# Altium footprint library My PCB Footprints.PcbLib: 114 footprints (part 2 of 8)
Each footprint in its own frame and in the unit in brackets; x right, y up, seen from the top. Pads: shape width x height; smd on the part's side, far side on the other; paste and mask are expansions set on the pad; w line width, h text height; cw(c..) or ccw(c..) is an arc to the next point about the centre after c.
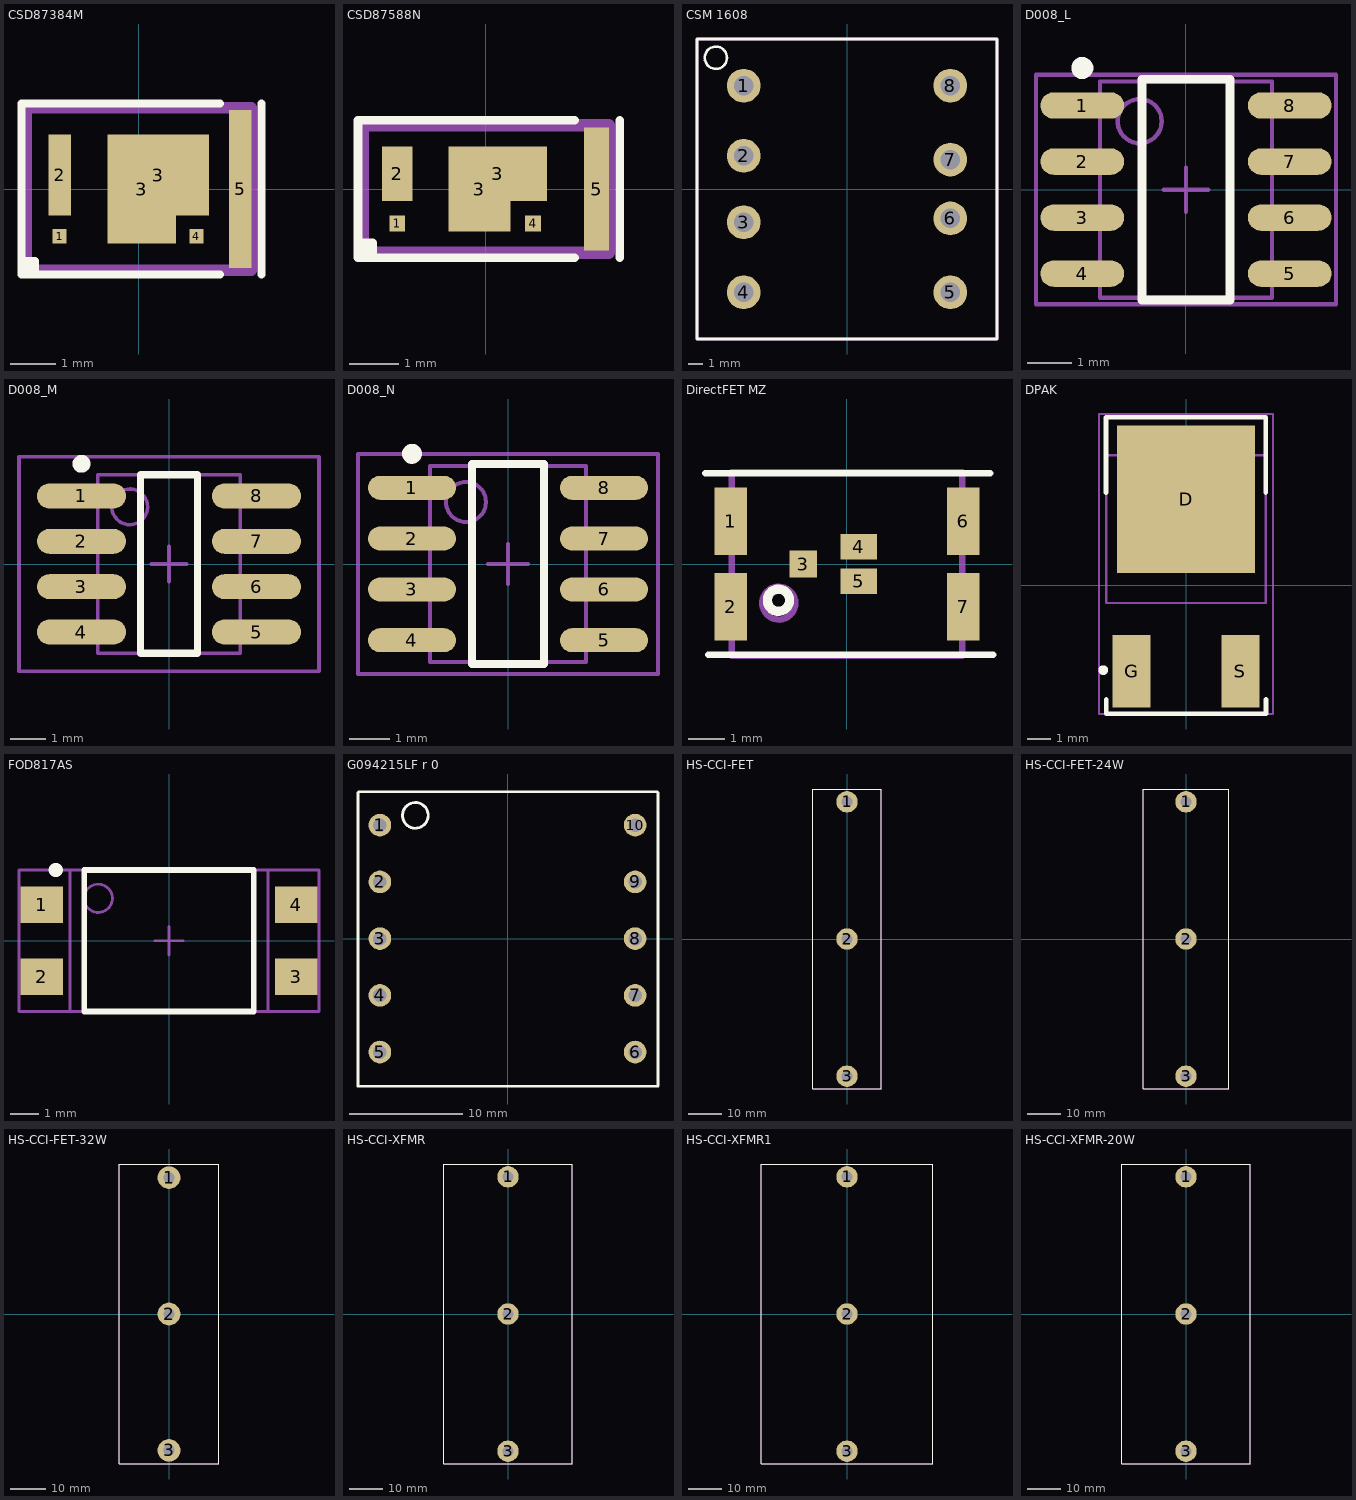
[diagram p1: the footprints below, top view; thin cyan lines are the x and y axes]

## CSD87384M [mm] "TI recommended land pattern SLPS-JUNE 2012"
height 0.45
pads (6):
  rect 0.32x0.32 smd paste+0 mask+0.051: 1(-1.76,-1.05) 4(1.28,-1.05)
  rect 0.5x1.8 smd paste-0.1 mask+0.051: 2(-1.76,0.31)
  rect 1.52x2.42 smd paste-1.5 mask+0.051: 3(0.06,0)
  rect 2.26x1.8 smd paste-2.2 mask+0.051: 3(0.43,0.31)
  rect 0.5x3.5 smd paste-0.5 mask+0.051: 5(2.25,0)
Top Overlay:
  lines w0.178: -2.6,-1.75 -2.3,-1.75 ; -2.6,-1.6 -2.3,-1.6 -2.3,-1.9 ; 1.8,-1.9 0,-1.9 -2.6,-1.9 -2.6,0 -2.6,1.9 0,1.9 1.8,1.9 ; 2.72,-1.9 2.72,0 2.72,1.9
Top Paste:
  region: -0.6,-0.39 -0.6,1.11 0.33,1.11 0.33,-0.39
  region: 1.46,-0.39 0.53,-0.39 0.53,1.11 1.46,1.11
  region: 2.08,-1.67 2.08,-0.1 2.42,-0.1 2.42,-1.67
  region: 2.08,0.1 2.08,1.67 2.42,1.67 2.42,0.1
  region: 0.72,-1.11 -0.6,-1.11 -0.6,-0.59 0.72,-0.59
Mechanical 5:
  text ".Designator" at -1.529,-0.508 h1.02
Mechanical 13:
  lines w0.254: -2.5,-1.8 2.5,-1.8 2.5,1.8 -2.5,1.8 -2.5,-1.8
3D body: height 1.5, standoff 0, extent -2.5,-1.8 2.5,1.8
3D body: height 1.5, standoff 1.5, extent -2.5,-1.8 0,0

## CSD87588N [mm] "TI recommended land pattern SLPS-JUNE 2012"
height 0.45
pads (6):
  rect 0.32x0.32 smd paste+0 mask+0.051: 1(-1.8,-0.7) 4(0.96,-0.7)
  rect 0.62x1.1 smd paste-0.1 mask+0.051: 2(-1.8,0.31)
  rect 1.26x1.72 smd paste-1.5 mask+0.051: 3(-0.13,0)
  rect 2x1.1 smd paste-2.2 mask+0.051: 3(0.24,0.31)
  rect 0.5x2.5 smd paste-0.08 mask+0.051: 5(2.25,0)
Top Overlay:
  lines w0.178: -2.6,-1.25 -2.3,-1.25 ; -2.6,-1.1 -2.3,-1.1 -2.3,-1.4 ; 1.8,-1.4 0,-1.4 -2.6,-1.4 -2.6,0 -2.6,1.4 0,1.4 1.8,1.4 ; 2.72,-1.4 2.72,0 2.72,1.4
Top Paste:
  region: 0.4,-0.76 -0.66,-0.76 -0.66,-0.34 0.4,-0.34
  region: 1.14,-0.14 0.34,-0.14 0.34,0.76 1.14,0.76
  region: -0.66,-0.14 -0.66,0.76 0.14,0.76 0.14,-0.14
Mechanical 5:
  text ".Designator" at -1.529,-0.508 h1.02
Mechanical 13:
  lines w0.254: -2.5,-1.3 -2.5,1.3 2.5,1.3 2.5,-1.3 -2.5,-1.3
3D body: height 1.5, standoff 1.5, extent -2.5,-1.3 0,0
3D body: height 1.5, standoff 0, extent -2.5,-1.3 2.5,1.3

## CSM 1608 [mil] "Cramer Coil Offline Flyback Transformer"
height 650
pads (8):
  round 90 hole 52: 1(-275.5,275.5) 2(-275.5,88.5) 3(-275.5,-88.5) 4(-275.5,-275.5) 5(275.5,-275.5) 6(275.5,-78.5) 7(275.5,78.5) 8(275.5,275.5)
Top Overlay:
  circle w7: c-349.73,350 r29.73
  lines w7: -400,-400 400,-400 400,400 -400,400 -400,-400
Mechanical 5:
  text ".designator" at -48,-25 h60
Mechanical 13:
  lines w7: -400,-400 400,-400 400,400 -400,400 -400,-400
3D body: height 600, standoff 50, extent -400,-400 400,400
3D body: height 650, standoff 649, extent -378.06,321.46 -318.12,381.4

## D008_L [mm] "8-Pin Small Outline Integrated Circuit 1.27 mm Pitch, IPC High Density"
height 1.75
pads (8):
  oval 1.9x0.6 smd: 1(-2.35,1.905) 2(-2.35,0.635) 3(-2.35,-0.635) 4(-2.35,-1.905) 5(2.35,-1.905) 6(2.35,-0.635) 7(2.35,0.635) 8(2.35,1.905)
Top Overlay:
  circle w0.25: c-2.35,2.755 r0.125
  lines w0.2: -1,-2.5 -1,2.5 1,2.5 1,-2.5 -1,-2.5
Mechanical 5:
  text ".Designator" at -0.254,1.524 h1.02
Mechanical 13:
  circle w0.1: c-1.05,1.55 r0.5
  lines w0.1: -1.95,-2.45 -1.95,2.45 1.95,2.45 1.95,-2.45 -1.95,-2.45
Mechanical 15:
  lines w0.1: -0.5,0 0.5,0 ; 0,-0.5 0,0.5 ; -3.4,-2.6 -3.4,2.6 3.4,2.6 3.4,-2.6 -3.4,-2.6
3D body: height 1.75, standoff 0, extent -1.95,-2.45 1.95,2.45

## D008_M [mm] "8-Pin Small Outline Integrated Circuit 1.27 mm Pitch, IPC Low Density"
height 1.75
pads (8):
  oval 2.5x0.7 smd: 1(-2.45,1.905) 2(-2.45,0.635) 3(-2.45,-0.635) 4(-2.45,-1.905) 5(2.45,-1.905) 6(2.45,-0.635) 7(2.45,0.635) 8(2.45,1.905)
Top Overlay:
  circle w0.25: c-2.45,2.805 r0.125
  lines w0.2: -0.8,-2.5 0.8,-2.5 0.8,2.5 -0.8,2.5 -0.8,-2.5
Mechanical 5:
  text ".Designator" at -0.254,1.524 h1.02
Mechanical 13:
  circle w0.1: c-1.1,1.6 r0.5
  lines w0.1: -2,-2.5 2,-2.5 2,2.5 -2,2.5 -2,-2.5
Mechanical 15:
  lines w0.1: -0.5,0 0.5,0 ; 0,-0.5 0,0.5 ; -4.2,-3 4.2,-3 4.2,3 -4.2,3 -4.2,-3
3D body: height 1.75, standoff 0, extent -2,-2.5 2,2.5

## D008_N [mm] "8-Pin Small Outline Integrated Circuit 1.27 mm Pitch, IPC Medium Density"
height 1.75
pads (8):
  oval 2.2x0.6 smd: 1(-2.4,1.905) 2(-2.4,0.635) 3(-2.4,-0.635) 4(-2.4,-1.905) 5(2.4,-1.905) 6(2.4,-0.635) 7(2.4,0.635) 8(2.4,1.905)
Top Overlay:
  circle w0.25: c-2.4,2.755 r0.125
  lines w0.2: -0.9,-2.5 -0.9,2.5 0.9,2.5 0.9,-2.5 -0.9,-2.5
Mechanical 5:
  text ".Designator" at -0.254,1.524 h1.02
Mechanical 13:
  circle w0.1: c-1.05,1.55 r0.5
  lines w0.1: -1.95,-2.45 -1.95,2.45 1.95,2.45 1.95,-2.45 -1.95,-2.45
Mechanical 15:
  lines w0.1: -0.5,0 0.5,0 ; 0,-0.5 0,0.5 ; -3.75,-2.75 -3.75,2.75 3.75,2.75 3.75,-2.75 -3.75,-2.75
3D body: height 1.75, standoff 0, extent -1.95,-2.45 1.95,2.45

## DirectFET MZ [mm] "International Rectifier DirectFET MZ footprint"
height 0.7
pads (7):
  rect 0.9x1.85 smd: 1(-3.2,1.175) 2(-3.2,-1.175) 6(3.2,1.175) 7(3.2,-1.175)
  rect 0.75x0.75 smd: 3(-1.2,0)
  rect 1x0.7 smd: 4(0.325,0.475) 5(0.325,-0.475)
Top Overlay:
  circle w0.254: c-1.885,-0.997 r0.305
  lines w0.178: -3.899,2.5 3.939,2.5 ; -3.818,-2.5 4.02,-2.5
Mechanical 5:
  text ".Designator" at -1.524,-0.508 h1.02
Mechanical 13:
  circle w0.178: c-1.875,-1.075 r0.453
  lines w0.178: -3.175,-2.525 -3.175,0 -3.175,2.525 0,2.525 3.175,2.525 3.175,0 3.175,-2.525 0,-2.525 -3.175,-2.525
3D body: height 0.7, standoff 0.7, extent -2.336,-1.536 -1.414,-0.614
3D body: height 0.7, standoff 0, extent -3.174,-2.524 3.174,2.524

## DPAK [mm]
pads (3):
  rect 5.8x6.2 smd: D(0,3.61)
  rect 1.6x3.05 smd: G(-2.28,-3.61) S(2.28,-3.61)
Top Overlay:
  circle w0.254: c-3.47,-3.559 r0.077
  lines w0.2: -3.353,3.898 -3.353,7.044 3.347,7.044 3.347,3.898 ; -3.346,-4.792 -3.346,-5.392 3.354,-5.392 3.354,-4.792
Mechanical 5:
  text ".designator" at 0.483,-0.794 h0.89
Mechanical 13:
  lines w0.1: -3.35,-0.74 3.35,-0.74 3.35,5.46 -3.35,5.46 -3.35,-0.74
Mechanical 15:
  lines w0.1: -0.5,1.36 0.5,1.36 ; 0,0.86 0,1.86 ; -3.65,-5.398 3.65,-5.398 3.65,7.185 -3.65,7.185 -3.65,-5.398
3D body: height 2.39, standoff 0.13, extent -3.35,-0.74 3.35,5.46

## FOD817AS [mm] "FOD817AS recommended footprint"
height 4
pads (4):
  rect 1.5x1.3 smd: 1(-4.5,1.27) 2(-4.5,-1.27) 3(4.5,-1.27) 4(4.5,1.27)
Top Overlay:
  circle w0.25: c-4,2.5 r0.125
  lines w0.2: -3,-2.5 3,-2.5 3,2.5 -3,2.5 -3,-2.5
Mechanical 5:
  text ".Designator" at -1.524,-0.508 h1.02
Mechanical 13:
  circle w0.1: c-2.5,1.5 r0.5
  lines w0.1: -3.5,-2.5 3.5,-2.5 3.5,2.5 -3.5,2.5 -3.5,-2.5
Mechanical 15:
  lines w0.1: -0.5,0 0.5,0 ; 0,-0.5 0,0.5 ; -5.3,-2.5 5.3,-2.5 5.3,2.5 -5.3,2.5 -5.3,-2.5
3D body: height 4, standoff 0, extent -3.009,0.991 -1.991,2.009
3D body: height 4, standoff 0, extent -3.5,-2.5 3.5,2.5

## G094215LF r 0 [mm]
pads (10):
  round 2 hole 1.2: 1(-11.25,10) 2(-11.25,5) 3(-11.25,0) 4(-11.25,-5) 5(-11.25,-10) 6(11.25,-10) 7(11.25,-5) 8(11.25,0) 9(11.25,5) 10(11.25,10)
Top Overlay:
  circle w0.254: c-8.126,10.864 r1.133
  lines w0.254: -13.18,12.87 -13.18,-13.012 13.236,-13.012 13.261,-12.987 13.261,12.87 ; -13.104,12.946 13.185,12.946

## HS-CCI-FET [mm] "CCI MOSFET heat sink"
height 25.4
pads (3):
  round 6.35 hole 3.175: 1(0,40.64) 2(0,0) 3(0,-40.64)
Top Overlay:
  lines w0.178: -10.16,-44.45 -10.16,0 -10.16,44.45 0,44.45 10.16,44.45 10.16,0 10.16,-44.45 0,-44.45 -10.16,-44.45
Mechanical 5:
  text ".designator" at -1.219,-0.635 h1.52
Mechanical 13:
  lines w0.178: -10.16,-44.45 10.16,-44.45 10.16,44.45 -10.16,44.45 -10.16,-44.45
3D body: height 25.4, standoff 1.27, extent -10.16,-44.45 10.16,44.45

## HS-CCI-FET-24W [mm] "CCI MOSFET 24W heat sink"
height 25.4
pads (3):
  round 6.35 hole 3.175: 1(0,40.64) 2(0,0) 3(0,-40.64)
Top Overlay:
  lines w0.178: -12.7,-44.45 -12.7,0 -12.7,44.45 0,44.45 12.7,44.45 12.7,0 12.7,-44.45 0,-44.45 -12.7,-44.45
Mechanical 5:
  text ".designator" at -1.219,-0.635 h1.52
Mechanical 13:
  lines w0.178: -12.7,-44.45 12.7,-44.45 12.7,44.45 -12.7,44.45 -12.7,-44.45
3D body: height 25.4, standoff 1.27, extent -12.7,-44.45 12.7,44.45

## HS-CCI-FET-32W [mm] "CCI MOSFET 32W heat sink"
height 25.4
pads (3):
  round 6.35 hole 3.175: 1(0,38.1) 2(0,0) 3(0,-38.1)
Top Overlay:
  lines w0.178: -13.97,-41.91 -13.97,0 -13.97,41.91 0,41.91 13.97,41.91 13.97,0 13.97,-41.91 0,-41.91 -13.97,-41.91
Mechanical 5:
  text ".designator" at -1.219,-0.635 h1.52
Mechanical 13:
  lines w0.178: -13.97,-41.91 13.97,-41.91 13.97,41.91 -13.97,41.91 -13.97,-41.91
3D body: height 25.4, standoff 1.27, extent -13.97,-41.91 13.97,41.91

## HS-CCI-XFMR [mm] "CCI Transformer heat sink"
height 25.4
pads (3):
  round 6.35 hole 3.175: 1(0,40.64) 2(0,0) 3(0,-40.64)
Top Overlay:
  lines w0.178: -19.05,-44.45 0,-44.45 19.05,-44.45 19.05,0 19.05,44.45 0,44.45 -19.05,44.45 -19.05,0 -19.05,-44.45
Mechanical 5:
  text ".designator" at -1.219,-0.635 h1.52
Mechanical 13:
  lines w0.178: -19.05,-44.45 -19.05,44.45 19.05,44.45 19.05,-44.45 -19.05,-44.45
3D body: height 25.4, standoff 16.51, extent -19.05,-44.45 19.05,44.45

## HS-CCI-XFMR1 [mm] "CCI transformer heat sink"
height 25.4
pads (3):
  round 6.35 hole 3.175: 1(0,40.64) 2(0,0) 3(0,-40.64)
Top Overlay:
  lines w0.178: -25.4,-44.45 0,-44.45 25.4,-44.45 25.4,0 25.4,44.45 0,44.45 -25.4,44.45 -25.4,0 -25.4,-44.45
Mechanical 5:
  text ".designator" at -1.219,-0.635 h1.52
Mechanical 13:
  lines w0.178: -25.4,-44.45 -25.4,44.45 25.4,44.45 25.4,-44.45 -25.4,-44.45
3D body: height 25.4, standoff 16.51, extent -25.4,-44.45 25.4,44.45

## HS-CCI-XFMR-20W [mm] "CCI Transformer 20W heat sink"
height 25.4
pads (3):
  round 6.35 hole 3.175: 1(0,40.64) 2(0,0) 3(0,-40.64)
Top Overlay:
  lines w0.178: -19.05,-44.45 -19.05,0 -19.05,44.45 0,44.45 19.05,44.45 19.05,0 19.05,-44.45 0,-44.45 -19.05,-44.45
Mechanical 5:
  text ".designator" at -1.219,-0.635 h1.52
Mechanical 13:
  lines w0.178: -19.05,-44.45 19.05,-44.45 19.05,44.45 -19.05,44.45 -19.05,-44.45
3D body: height 25.4, standoff 16.51, extent -19.05,-44.45 19.05,44.45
